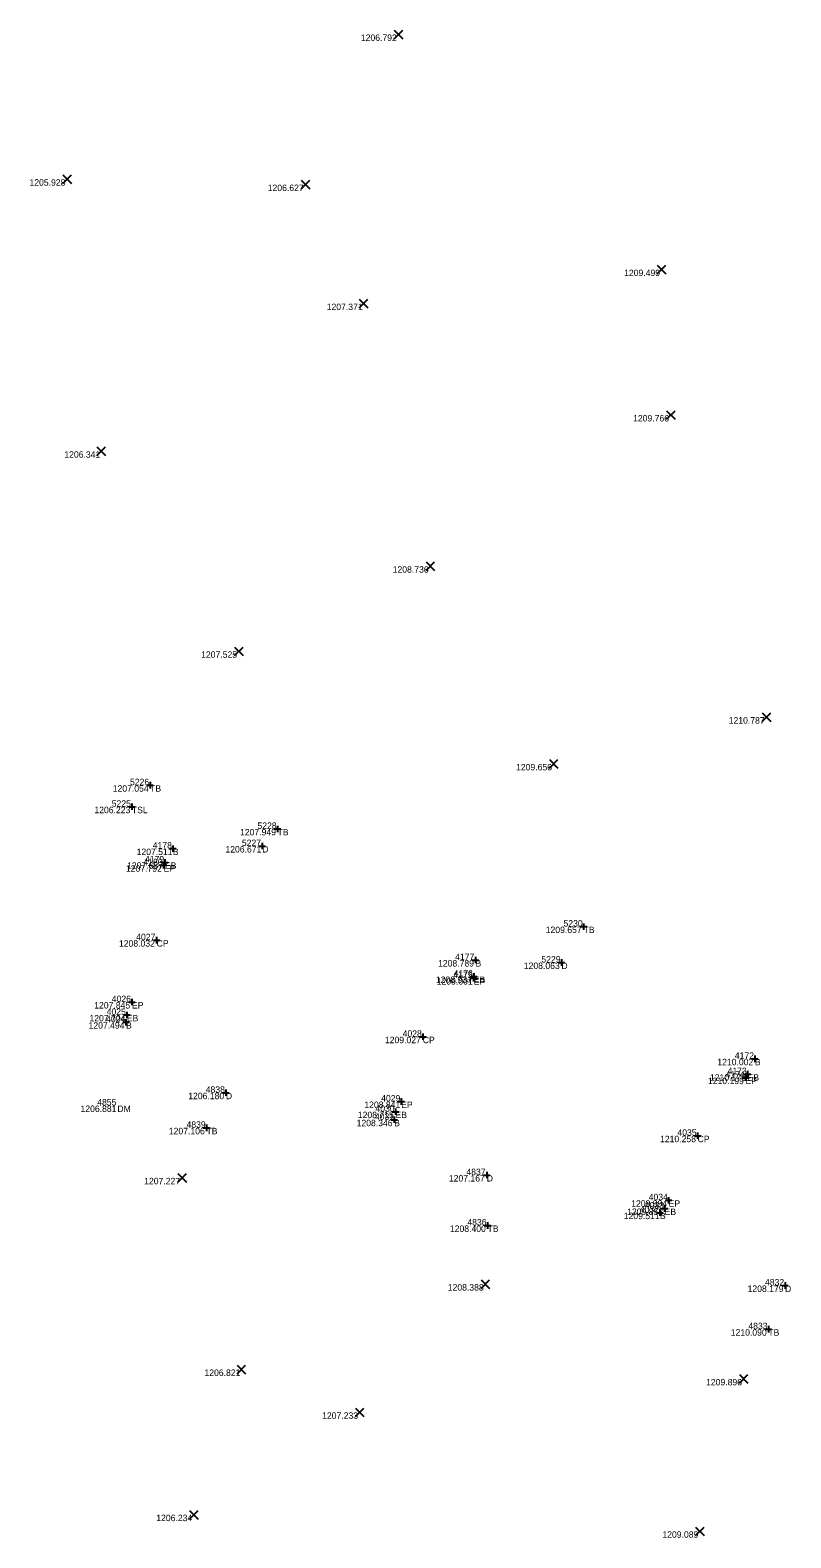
# Model space of a CAD drawing. Extents: x 2044997 to 2050342, y 455233 to 458054.
# Drawn here: x 2047745.7 to 2047863.8, y 456853.1 to 457087 of the extents above; entities that cross this region are included whole.
import ezdxf

# ---------------------------------------------------------------- set-up
doc = ezdxf.new("R2010")
doc.units = 0
for name, color, linetype in [('SV_X_Random_Point', 7, 'Continuous'), ('SV_X_Shot_Marker', 7, 'Continuous'), ('SV_X_Text_Comment', 7, 'Continuous'), ('SV_X_Text_Elevation', 7, 'Continuous'), ('SV_X_Text_Name', 7, 'Continuous')]:
    doc.layers.add(name, color=color, linetype=linetype)

msp = doc.modelspace()

# ---------------------------------------------------------------- linework, layer by layer
at = {"layer": 'SV_X_Random_Point'}
for p, q in [((2047802.23, 457085.65), (2047803.56, 457086.99)), ((2047802.23, 457086.99), (2047803.56, 457085.65)), ((2047750.8, 457063.19), (2047752.13, 457064.53)), ((2047750.8, 457064.53), (2047752.13, 457063.19)), ((2047787.82, 457062.36), (2047789.15, 457063.7)), ((2047787.82, 457063.7), (2047789.15, 457062.36)), ((2047843.07, 457049.17), (2047844.4, 457050.51)), ((2047843.07, 457050.51), (2047844.4, 457049.17)), ((2047796.81, 457043.89), (2047798.14, 457045.23)), ((2047796.81, 457045.23), (2047798.14, 457043.89)), ((2047844.49, 457026.62), (2047845.82, 457027.95)), ((2047844.49, 457027.95), (2047845.82, 457026.62)), ((2047756.09, 457020.99), (2047757.42, 457022.33)), ((2047756.09, 457022.33), (2047757.42, 457020.99)), ((2047807.17, 457003.16), (2047808.51, 457004.49)), ((2047807.17, 457004.49), (2047808.51, 457003.16)), ((2047777.45, 456989.95), (2047778.79, 456991.29)), ((2047777.45, 456991.29), (2047778.79, 456989.95)), ((2047859.36, 456979.74), (2047860.69, 456981.08)), ((2047859.36, 456981.08), (2047860.69, 456979.74)), ((2047826.32, 456972.49), (2047827.65, 456973.82)), ((2047826.32, 456973.82), (2047827.65, 456972.49)), ((2047768.65, 456908.27), (2047769.98, 456909.61)), ((2047768.65, 456909.61), (2047769.98, 456908.27)), ((2047815.72, 456891.78), (2047817.05, 456893.11)), ((2047815.72, 456893.11), (2047817.05, 456891.78)), ((2047777.84, 456878.54), (2047779.18, 456879.87)), ((2047777.84, 456879.87), (2047779.18, 456878.54)), ((2047855.81, 456877.08), (2047857.14, 456878.41)), ((2047855.81, 456878.41), (2047857.14, 456877.08)), ((2047796.21, 456871.89), (2047797.54, 456873.23)), ((2047796.21, 456873.23), (2047797.54, 456871.89)), ((2047770.45, 456856.01), (2047771.79, 456857.35)), ((2047770.45, 456857.35), (2047771.79, 456856.01)), ((2047849.01, 456853.44), (2047850.34, 456854.77)), ((2047849.01, 456854.77), (2047850.34, 456853.44))]:
    msp.add_line(p, q, dxfattribs=at)
at = {"layer": 'SV_X_Shot_Marker'}
for p, q in [((2047763.85, 456969.85), (2047764.85, 456969.85)), ((2047764.35, 456970.35), (2047764.35, 456969.35)), ((2047764.35, 456969.85), (2047764.35, 456969.85)), ((2047761.53, 456967.01), (2047761.53, 456966.01)), ((2047761.03, 456966.51), (2047762.03, 456966.51)), ((2047761.53, 456966.51), (2047761.53, 456966.51)), ((2047783.63, 456963.07), (2047784.63, 456963.07)), ((2047784.13, 456963.57), (2047784.13, 456962.57)), ((2047784.13, 456963.07), (2047784.13, 456963.07)), ((2047767.38, 456960.02), (2047768.38, 456960.02)), ((2047767.88, 456960.52), (2047767.88, 456959.52)), ((2047767.88, 456960.02), (2047767.88, 456960.02)), ((2047781.26, 456960.41), (2047782.26, 456960.41)), ((2047781.76, 456960.91), (2047781.76, 456959.91)), ((2047781.76, 456960.41), (2047781.76, 456960.41)), ((2047766.15, 456957.88), (2047767.15, 456957.88)), ((2047766.43, 456957.93), (2047766.43, 456956.93)), ((2047766.65, 456958.38), (2047766.65, 456957.38)), ((2047766.65, 456957.88), (2047766.65, 456957.88)), ((2047765.93, 456957.43), (2047766.93, 456957.43)), ((2047766.43, 456957.43), (2047766.43, 456957.43)), ((2047831.63, 456948.42), (2047831.63, 456947.42)), ((2047765.36, 456946.31), (2047765.36, 456945.31)), ((2047831.13, 456947.92), (2047832.13, 456947.92)), ((2047831.63, 456947.92), (2047831.63, 456947.92)), ((2047764.86, 456945.81), (2047765.86, 456945.81)), ((2047765.36, 456945.81), (2047765.36, 456945.81)), ((2047814.35, 456942.72), (2047815.35, 456942.72)), ((2047814.85, 456943.22), (2047814.85, 456942.22)), ((2047814.85, 456942.72), (2047814.85, 456942.72)), ((2047827.68, 456942.34), (2047828.68, 456942.34)), ((2047828.18, 456942.84), (2047828.18, 456941.84)), ((2047828.18, 456942.34), (2047828.18, 456942.34)), ((2047814.05, 456939.92), (2047815.05, 456939.92)), ((2047814.09, 456940.17), (2047815.09, 456940.17)), ((2047814.55, 456940.42), (2047814.55, 456939.42)), ((2047814.55, 456939.92), (2047814.55, 456939.92)), ((2047814.59, 456940.67), (2047814.59, 456939.67)), ((2047814.59, 456940.17), (2047814.59, 456940.17)), ((2047761.53, 456936.71), (2047761.53, 456935.71)), ((2047760.74, 456934.71), (2047760.74, 456933.71)), ((2047761.03, 456936.21), (2047762.03, 456936.21)), ((2047761.53, 456936.21), (2047761.53, 456936.21)), ((2047760.11, 456933.08), (2047761.11, 456933.08)), ((2047760.24, 456934.21), (2047761.24, 456934.21)), ((2047760.61, 456933.58), (2047760.61, 456932.58)), ((2047760.61, 456933.08), (2047760.61, 456933.08)), ((2047760.74, 456934.21), (2047760.74, 456934.21)), ((2047806.17, 456930.83), (2047807.17, 456930.83)), ((2047806.67, 456931.33), (2047806.67, 456930.33)), ((2047806.67, 456930.83), (2047806.67, 456930.83)), ((2047857.71, 456927.41), (2047858.71, 456927.41)), ((2047858.21, 456927.91), (2047858.21, 456926.91)), ((2047858.21, 456927.41), (2047858.21, 456927.41)), ((2047856.58, 456925.02), (2047857.58, 456925.02)), ((2047856.75, 456924.98), (2047856.75, 456923.98)), ((2047857.08, 456925.52), (2047857.08, 456924.52)), ((2047857.08, 456925.02), (2047857.08, 456925.02)), ((2047776.11, 456922.64), (2047776.11, 456921.64)), ((2047856.25, 456924.48), (2047857.25, 456924.48)), ((2047856.75, 456924.48), (2047856.75, 456924.48)), ((2047775.61, 456922.14), (2047776.61, 456922.14)), ((2047776.11, 456922.14), (2047776.11, 456922.14)), ((2047802.81, 456920.78), (2047803.81, 456920.78)), ((2047803.31, 456921.28), (2047803.31, 456920.28)), ((2047803.31, 456920.78), (2047803.31, 456920.78)), ((2047801.74, 456917.95), (2047802.74, 456917.95)), ((2047801.94, 456919.2), (2047802.94, 456919.2)), ((2047802.24, 456918.45), (2047802.24, 456917.45)), ((2047802.24, 456917.95), (2047802.24, 456917.95)), ((2047802.44, 456919.7), (2047802.44, 456918.7)), ((2047802.44, 456919.2), (2047802.44, 456919.2)), ((2047772.6, 456916.7), (2047773.6, 456916.7)), ((2047773.1, 456917.2), (2047773.1, 456916.2)), ((2047773.1, 456916.7), (2047773.1, 456916.7)), ((2047849.32, 456915.97), (2047849.32, 456914.97)), ((2047848.82, 456915.47), (2047849.82, 456915.47)), ((2047849.32, 456915.47), (2047849.32, 456915.47)), ((2047816.1, 456909.37), (2047817.1, 456909.37)), ((2047816.6, 456909.87), (2047816.6, 456908.87)), ((2047816.6, 456909.37), (2047816.6, 456909.37)), ((2047843.48, 456904.03), (2047843.48, 456903.03)), ((2047843.7, 456904.18), (2047844.7, 456904.18)), ((2047844.2, 456904.68), (2047844.2, 456903.68)), ((2047844.2, 456904.18), (2047844.2, 456904.18)), ((2047844.32, 456905.46), (2047845.32, 456905.46)), ((2047844.82, 456905.96), (2047844.82, 456904.96)), ((2047844.82, 456905.46), (2047844.82, 456905.46)), ((2047816.22, 456901.55), (2047817.22, 456901.55)), ((2047816.72, 456902.05), (2047816.72, 456901.05)), ((2047816.72, 456901.55), (2047816.72, 456901.55)), ((2047842.98, 456903.53), (2047843.98, 456903.53)), ((2047843.48, 456903.53), (2047843.48, 456903.53)), ((2047862.39, 456892.24), (2047863.39, 456892.24)), ((2047862.89, 456892.74), (2047862.89, 456891.74)), ((2047862.89, 456892.24), (2047862.89, 456892.24)), ((2047859.8, 456885.46), (2047860.8, 456885.46)), ((2047860.3, 456885.96), (2047860.3, 456884.96)), ((2047860.3, 456885.46), (2047860.3, 456885.46))]:
    msp.add_line(p, q, dxfattribs=at)

# ---------------------------------------------------------------- texts
at = {"layer": 'SV_X_Text_Comment'}
for s, p in [('TB', (2047764.35, 456968.85)), ('TSL', (2047761.53, 456965.51)), ('TB', (2047784.13, 456962.07)), ('B', (2047767.88, 456959.02)), ('D', (2047781.76, 456959.41)), ('EB', (2047766.65, 456956.88)), ('EP', (2047766.43, 456956.43)), ('TB', (2047831.63, 456946.92)), ('CP', (2047765.36, 456944.81)), ('B', (2047814.85, 456941.72)), ('D', (2047828.18, 456941.34)), ('EP', (2047814.55, 456938.92)), ('EB', (2047814.59, 456939.17)), ('EP', (2047761.53, 456935.21)), ('B', (2047760.61, 456932.08)), ('EB', (2047760.74, 456933.21)), ('CP', (2047806.67, 456929.83)), ('B', (2047858.21, 456926.41)), ('EB', (2047857.08, 456924.02)), ('EP', (2047856.75, 456923.48)), ('D', (2047776.11, 456921.14)), ('EP', (2047803.31, 456919.78)), ('DM', (2047759.27, 456919.16)), ('B', (2047802.24, 456916.95)), ('EB', (2047802.44, 456918.2)), ('TB', (2047773.1, 456915.7)), ('CP', (2047849.32, 456914.47)), ('D', (2047816.6, 456908.37)), ('EB', (2047844.2, 456903.18)), ('EP', (2047844.82, 456904.46)), ('TB', (2047816.72, 456900.55)), ('B', (2047843.48, 456902.53)), ('D', (2047862.89, 456891.24)), ('TB', (2047860.3, 456884.46))]:
    msp.add_text(s, height=1, dxfattribs=at).set_placement(p)
at = {"layer": 'SV_X_Text_Elevation'}
for s, p in [('1206.792', (2047797.06, 457085.32)), ('1205.928', (2047745.63, 457062.86)), ('1206.627', (2047782.61, 457062.03)), ('1209.499', (2047837.92, 457048.84)), ('1207.371', (2047791.76, 457043.56)), ('1209.766', (2047839.31, 457026.28)), ('1206.341', (2047751.04, 457020.66)), ('1208.736', (2047802, 457002.82)), ('1207.525', (2047772.27, 456989.62)), ('1210.787', (2047854.15, 456979.41)), ('1209.656', (2047821.15, 456972.15)), ('1207.054', (2047758.55, 456968.85)), ('1206.223', (2047755.7, 456965.51)), ('1207.949', (2047778.31, 456962.07)), ('1207.511', (2047762.26, 456959.02)), ('1206.671', (2047776.04, 456959.41)), ('1207.687', (2047760.77, 456956.88)), ('1207.792', (2047760.6, 456956.43)), ('1209.657', (2047825.75, 456946.92)), ('1208.032', (2047759.52, 456944.81)), ('1208.789', (2047809.04, 456941.72)), ('1208.063', (2047822.35, 456941.34)), ('1208.937', (2047808.71, 456939.17)), ('1209.001', (2047808.84, 456938.92)), ('1207.704', (2047754.94, 456933.21)), ('1207.845', (2047755.68, 456935.21)), ('1207.494', (2047754.8, 456932.08)), ('1209.027', (2047800.79, 456929.83)), ('1210.002', (2047852.38, 456926.41)), ('1210.178', (2047851.24, 456924.02)), ('1210.199', (2047850.93, 456923.48)), ('1206.180', (2047770.27, 456921.14)), ('1208.841', (2047797.6, 456919.78)), ('1206.881', (2047753.55, 456919.16)), ('1208.346', (2047796.4, 456916.95)), ('1208.715', (2047796.59, 456918.2)), ('1207.106', (2047767.26, 456915.7)), ('1210.258', (2047843.49, 456914.47)), ('1207.227', (2047763.43, 456907.94)), ('1207.167', (2047810.72, 456908.37)), ('1209.853', (2047838.38, 456903.18)), ('1209.994', (2047839.02, 456904.46)), ('1208.400', (2047810.88, 456900.55)), ('1209.511', (2047837.86, 456902.53)), ('1208.388', (2047810.55, 456891.45)), ('1208.179', (2047857.08, 456891.24)), ('1210.090', (2047854.47, 456884.46)), ('1206.821', (2047772.79, 456878.21)), ('1209.896', (2047850.64, 456876.74)), ('1207.233', (2047791.05, 456871.56)), ('1206.234', (2047765.31, 456855.68)), ('1209.089', (2047843.86, 456853.1))]:
    msp.add_text(s, height=1, dxfattribs=at).set_placement(p)
at = {"layer": 'SV_X_Text_Name'}
for s, p in [('5226', (2047761.23, 456969.85)), ('5225', (2047758.4, 456966.51)), ('5228', (2047781.01, 456963.07)), ('4178', (2047764.76, 456960.02)), ('5227', (2047778.59, 456960.41)), ('4180', (2047763.31, 456957.43)), ('4179', (2047763.55, 456957.88)), ('5230', (2047828.51, 456947.92)), ('4027', (2047762.19, 456945.81)), ('4177', (2047811.69, 456942.72)), ('5229', (2047825.08, 456942.34)), ('4175', (2047811.42, 456939.92)), ('4176', (2047811.47, 456940.17)), ('4026', (2047758.4, 456936.21)), ('4025', (2047757.61, 456934.21)), ('4024', (2047757.52, 456933.08)), ('4028', (2047803.55, 456930.83)), ('4172', (2047855.1, 456927.41)), ('4174', (2047853.66, 456924.48)), ('4173', (2047853.97, 456925.02)), ('4838', (2047772.99, 456922.14)), ('4855', (2047756.14, 456920.16)), ('4030', (2047799.32, 456919.2)), ('4029', (2047800.21, 456920.78)), ('4031', (2047799.24, 456917.95)), ('4839', (2047770, 456916.7)), ('4035', (2047846.19, 456915.47)), ('4837', (2047813.44, 456909.37)), ('4034', (2047841.73, 456905.46)), ('4032', (2047840.36, 456903.53)), ('4033', (2047841.1, 456904.18)), ('4836', (2047813.59, 456901.55)), ('4832', (2047859.78, 456892.24)), ('4833', (2047857.2, 456885.46))]:
    msp.add_text(s, height=1, dxfattribs=at).set_placement(p)

doc.saveas('drawing.dxf')
